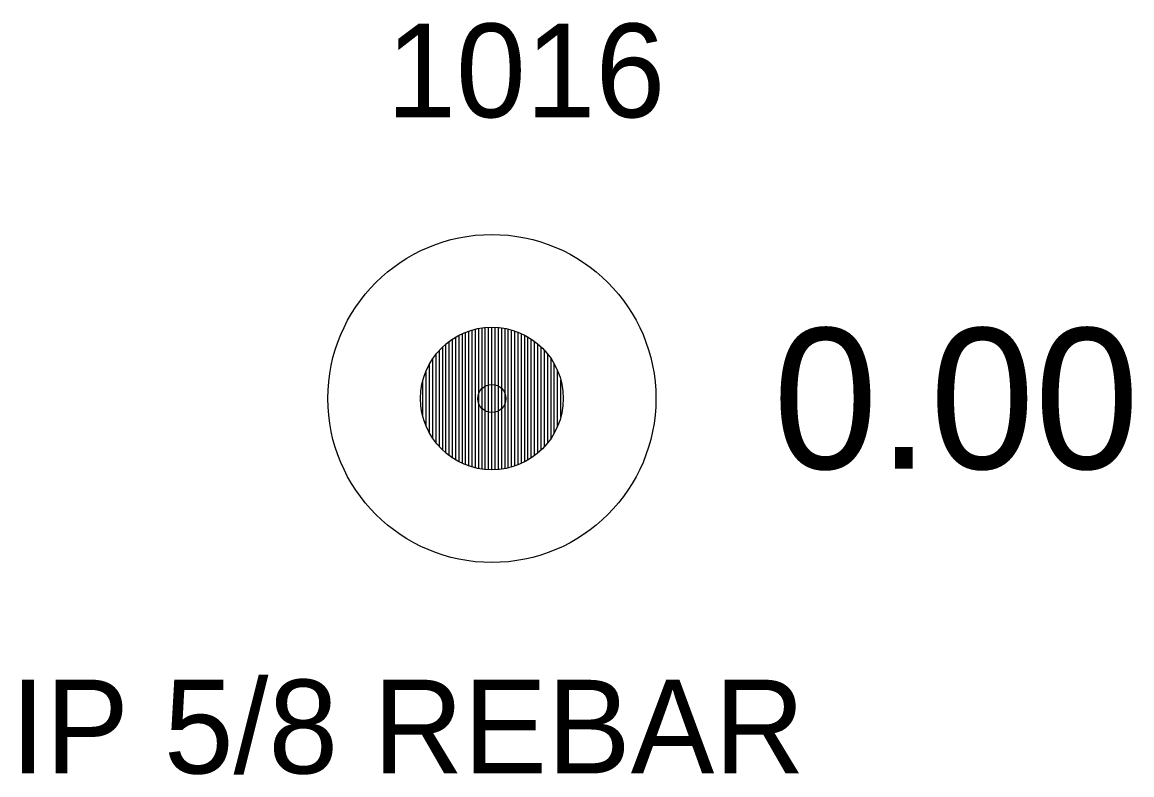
# Model space of a CAD drawing. Extents: x 1529475 to 1532053, y 876698 to 877911.
# Drawn here: x 1529875.69 to 1529887.52, y 877511.35 to 877519.38 of the extents above; entities that cross this region are included whole.
import ezdxf

# ---------------------------------------------------------------- set-up
doc = ezdxf.new("R2010")
doc.units = 0
for name, color, linetype in [('RD_EX_DV_Prop_txCode', 7, 'Continuous'), ('RD_EX_DV_PropPin', 7, 'Continuous'), ('RD_EX_TX_DV_Prop_ELEV', 7, 'Continuous'), ('RD_SMD_Locator', 7, 'Continuous')]:
    doc.layers.add(name, color=color, linetype=linetype)

msp = doc.modelspace()

# ---------------------------------------------------------------- linework, layer by layer
at = {"layer": 'RD_EX_DV_PropPin'}
for p, q in [((1529880.312, 877514.71), (1529880.312, 877516.023)), ((1529880.347, 877514.691), (1529880.347, 877516.042)), ((1529880.382, 877514.674), (1529880.382, 877516.059)), ((1529880.417, 877514.659), (1529880.417, 877516.074)), ((1529880.452, 877514.646), (1529880.452, 877516.087)), ((1529880.487, 877514.635), (1529880.487, 877516.098)), ((1529880.522, 877514.626), (1529880.522, 877516.107)), ((1529880.557, 877514.619), (1529880.557, 877516.115)), ((1529880.592, 877514.613), (1529880.592, 877516.12)), ((1529880.627, 877514.609), (1529880.627, 877516.124)), ((1529880.662, 877514.606), (1529880.662, 877516.127)), ((1529880.697, 877514.606), (1529880.697, 877516.128)), ((1529880.732, 877514.606), (1529880.732, 877516.127)), ((1529880.767, 877514.609), (1529880.767, 877516.124)), ((1529880.802, 877514.613), (1529880.802, 877516.12)), ((1529880.837, 877514.619), (1529880.837, 877516.115)), ((1529880.872, 877514.626), (1529880.872, 877516.107)), ((1529880.907, 877514.635), (1529880.907, 877516.098)), ((1529880.942, 877514.646), (1529880.942, 877516.087)), ((1529880.977, 877514.659), (1529880.977, 877516.074)), ((1529881.012, 877514.674), (1529881.012, 877516.059)), ((1529881.047, 877514.691), (1529881.047, 877516.042)), ((1529881.082, 877514.71), (1529881.082, 877516.023)), ((1529880.172, 877514.816), (1529880.172, 877515.917)), ((1529880.207, 877514.785), (1529880.207, 877515.949)), ((1529880.242, 877514.757), (1529880.242, 877515.977)), ((1529880.277, 877514.732), (1529880.277, 877516.001)), ((1529881.117, 877514.732), (1529881.117, 877516.001)), ((1529881.152, 877514.757), (1529881.152, 877515.977)), ((1529881.187, 877514.785), (1529881.187, 877515.949)), ((1529881.222, 877514.816), (1529881.222, 877515.917)), ((1529880.067, 877514.94), (1529880.067, 877515.793)), ((1529880.102, 877514.893), (1529880.102, 877515.841)), ((1529880.137, 877514.852), (1529880.137, 877515.882)), ((1529881.258, 877514.852), (1529881.258, 877515.882)), ((1529881.293, 877514.893), (1529881.293, 877515.841)), ((1529881.328, 877514.94), (1529881.328, 877515.793)), ((1529880.032, 877514.997), (1529880.032, 877515.736)), ((1529881.363, 877514.997), (1529881.363, 877515.736)), ((1529879.962, 877515.171), (1529879.962, 877515.563)), ((1529879.997, 877515.069), (1529879.997, 877515.665)), ((1529881.398, 877515.069), (1529881.398, 877515.665)), ((1529881.433, 877515.171), (1529881.433, 877515.563))]:
    msp.add_line(p, q, dxfattribs=at)
for radius in [1.75, 0.761]:
    msp.add_circle((1529880.697, 877515.367), radius, dxfattribs=at)
at = {"layer": 'RD_SMD_Locator'}
msp.add_circle((1529880.697, 877515.367), 0.15, dxfattribs=at)

# ---------------------------------------------------------------- texts
at = {"layer": 'RD_EX_DV_Prop_txCode'}
for s, p in [('1016', (1529879.571, 877518.367)), ('IP 5/8 REBAR', (1529875.563, 877511.367))]:
    msp.add_text(s, height=1, dxfattribs=at).set_placement(p)
at = {"layer": 'RD_EX_TX_DV_Prop_ELEV'}
msp.add_text('0.00', height=1.5, dxfattribs=at).set_placement((1529883.697, 877514.617))

doc.saveas('drawing.dxf')
